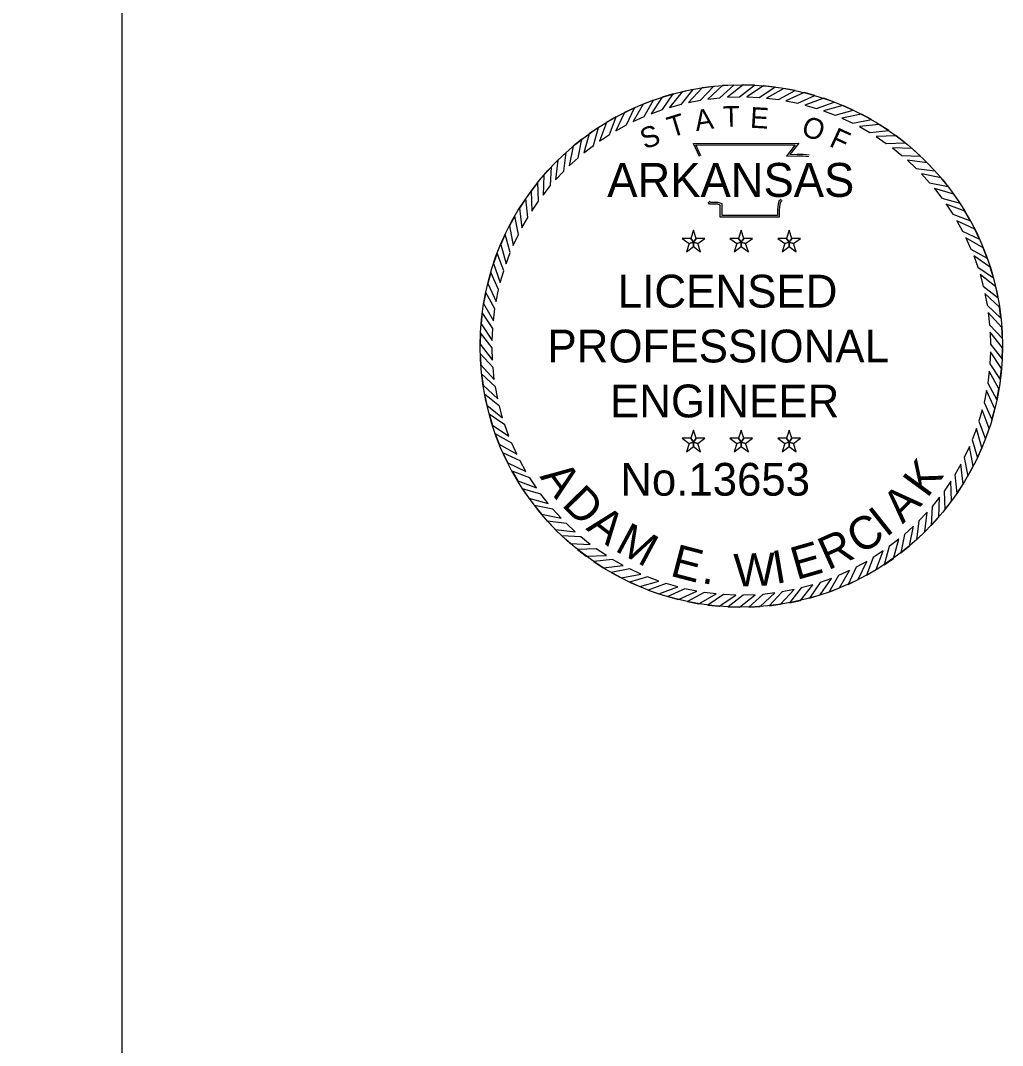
# Model space of a CAD drawing. Extents: x 0 to 19, y -0.6 to 11.2.
# Drawn here: x 16.766 to 19.022, y 5.302 to 7.658 of the extents above; entities that cross this region are included whole.
import ezdxf

# ---------------------------------------------------------------- set-up
doc = ezdxf.new("R2010")
doc.units = 0
for name, color, linetype in [('G-ANNO-STMP-AEW', 7, 'Continuous'), ('G-ANNO-TEXT', 7, 'Continuous'), ('G-Border-Paper', 7, 'Continuous'), ('G-No Plot-Stamp-1', 7, 'Continuous')]:
    doc.layers.add(name, color=color, linetype=linetype)

msp = doc.modelspace()

# ---------------------------------------------------------------- linework, layer by layer
at = {"layer": 'G-ANNO-STMP-AEW'}
for points in [[(18.3115, 7.4993), (18.2862, 7.494), (18.2576, 7.458), (18.2845, 7.4654)], [(18.3581, 7.5062), (18.3325, 7.5029), (18.3011, 7.4693), (18.3285, 7.4745)], [(18.4051, 7.5094), (18.3793, 7.5081), (18.3454, 7.477), (18.3731, 7.4801)], [(18.4522, 7.5089), (18.4264, 7.5096), (18.3902, 7.4813), (18.418, 7.4822)], [(18.4991, 7.5047), (18.4735, 7.5074), (18.4351, 7.4821), (18.463, 7.4808)], [(18.5456, 7.4968), (18.5202, 7.5016), (18.48, 7.4793), (18.5077, 7.4758)], [(18.5913, 7.4853), (18.5664, 7.4921), (18.5245, 7.473), (18.5518, 7.4674)], [(18.2206, 7.4747), (18.1965, 7.4655), (18.1738, 7.4255), (18.1992, 7.437)], [(18.2656, 7.4888), (18.2408, 7.4815), (18.2151, 7.4434), (18.2413, 7.4529)], [(18.6359, 7.4703), (18.6116, 7.479), (18.5684, 7.4632), (18.5952, 7.4555)], [(18.1769, 7.4572), (18.1536, 7.4461), (18.1341, 7.4044), (18.1585, 7.4179)], [(18.6793, 7.4518), (18.6557, 7.4624), (18.6114, 7.4501), (18.6375, 7.4402)], [(18.1347, 7.4362), (18.1123, 7.4234), (18.0962, 7.3803), (18.1195, 7.3956)], [(18.721, 7.43), (18.6984, 7.4423), (18.6532, 7.4336), (18.6784, 7.4217)], [(18.7609, 7.4049), (18.7393, 7.419), (18.6936, 7.4138), (18.7178, 7.4)], [(18.0942, 7.412), (18.0729, 7.3975), (18.0603, 7.3533), (18.0823, 7.3704)], [(18.0558, 7.3848), (18.0357, 7.3686), (18.0266, 7.3235), (18.0472, 7.3423)], [(18.7987, 7.3768), (18.7783, 7.3926), (18.7323, 7.391), (18.7554, 7.3753)], [(18.0197, 7.3545), (18.0009, 7.3368), (17.9953, 7.2912), (18.0144, 7.3115)], [(18.8342, 7.3458), (18.8151, 7.3632), (18.7692, 7.3652), (18.7909, 7.3477)], [(18.8672, 7.3122), (18.8495, 7.3309), (18.8038, 7.3365), (18.8242, 7.3175)], [(17.986, 7.3216), (17.9687, 7.3025), (17.9667, 7.2565), (17.9841, 7.2783)], [(18.8974, 7.276), (18.8812, 7.2961), (18.8361, 7.3053), (18.8549, 7.2847)], [(17.955, 7.2861), (17.9393, 7.2657), (17.9409, 7.2197), (17.9565, 7.2428)], [(18.9247, 7.2376), (18.9101, 7.2589), (18.8659, 7.2716), (18.883, 7.2496)], [(17.9269, 7.2483), (17.9128, 7.2267), (17.918, 7.181), (17.9318, 7.2052)], [(18.9489, 7.1972), (18.936, 7.2196), (18.893, 7.2357), (18.9083, 7.2124)], [(17.9019, 7.2084), (17.8895, 7.1857), (17.8983, 7.1406), (17.9102, 7.1658)], [(18.9698, 7.155), (18.9588, 7.1783), (18.9171, 7.1977), (18.9305, 7.1733)], [(17.88, 7.1666), (17.8695, 7.1431), (17.8818, 7.0988), (17.8916, 7.1248)], [(18.3125, 7.1485), (18.3187, 7.157), (18.3125, 7.176), (18.3064, 7.157)], [(18.4222, 7.1485), (18.4284, 7.157), (18.4222, 7.176), (18.4161, 7.157)], [(18.532, 7.1485), (18.5381, 7.157), (18.532, 7.176), (18.5258, 7.157)], [(18.3125, 7.1485), (18.3064, 7.157), (18.2864, 7.157), (18.3026, 7.1453)], [(18.3125, 7.1485), (18.3026, 7.1453), (18.2964, 7.1263), (18.3125, 7.1381)], [(18.3125, 7.1485), (18.3225, 7.1453), (18.3386, 7.157), (18.3187, 7.157)], [(18.3125, 7.1485), (18.3125, 7.1381), (18.3286, 7.1263), (18.3225, 7.1453)], [(18.4222, 7.1485), (18.4161, 7.157), (18.3962, 7.157), (18.4123, 7.1453)], [(18.4222, 7.1485), (18.4123, 7.1453), (18.4061, 7.1263), (18.4222, 7.1381)], [(18.4222, 7.1485), (18.4322, 7.1453), (18.4483, 7.157), (18.4284, 7.157)], [(18.4222, 7.1485), (18.4222, 7.1381), (18.4384, 7.1263), (18.4322, 7.1453)], [(18.532, 7.1485), (18.5258, 7.157), (18.5059, 7.157), (18.522, 7.1453)], [(18.532, 7.1485), (18.522, 7.1453), (18.5158, 7.1263), (18.532, 7.1381)], [(18.532, 7.1485), (18.5419, 7.1453), (18.5581, 7.157), (18.5381, 7.157)], [(18.532, 7.1485), (18.532, 7.1381), (18.5481, 7.1263), (18.5419, 7.1453)], [(18.9874, 7.1113), (18.9782, 7.1354), (18.9382, 7.158), (18.9496, 7.1326)], [(17.8615, 7.1233), (17.8529, 7.099), (17.8686, 7.0558), (17.8764, 7.0825)], [(19.0015, 7.0663), (18.9942, 7.0911), (18.9561, 7.1168), (18.9655, 7.0905)], [(17.8465, 7.0786), (17.8398, 7.0537), (17.8588, 7.0119), (17.8645, 7.0392)], [(19.012, 7.0204), (19.0067, 7.0456), (18.9707, 7.0742), (18.978, 7.0474)], [(17.835, 7.0329), (17.8303, 7.0076), (17.8526, 6.9674), (17.856, 6.995)], [(19.0188, 6.9738), (19.0155, 6.9993), (18.9819, 7.0307), (18.9871, 7.0033)], [(17.8272, 6.9865), (17.8244, 6.9608), (17.8498, 6.9225), (17.8511, 6.9503)], [(19.022, 6.9267), (19.0207, 6.9525), (18.9897, 6.9864), (18.9927, 6.9587)], [(17.823, 6.9396), (17.8222, 6.9138), (17.8505, 6.8775), (17.8497, 6.9054)], [(19.0215, 6.8796), (19.0223, 6.9054), (18.994, 6.9417), (18.9948, 6.9138)], [(17.8225, 6.8925), (17.8237, 6.8667), (17.8548, 6.8328), (17.8518, 6.8605)], [(19.0173, 6.8327), (19.0201, 6.8584), (18.9947, 6.8967), (18.9934, 6.8689)], [(17.8256, 6.8454), (17.829, 6.8199), (17.8626, 6.7885), (17.8574, 6.8159)], [(19.0095, 6.7863), (19.0142, 6.8116), (18.9919, 6.8518), (18.9884, 6.8242)], [(18.998, 6.7406), (19.0047, 6.7655), (18.9856, 6.8073), (18.98, 6.78)], [(17.8325, 6.7988), (17.8378, 6.7736), (17.8738, 6.745), (17.8665, 6.7718)], [(18.9829, 6.6959), (18.9916, 6.7202), (18.9759, 6.7634), (18.9681, 6.7367)], [(17.843, 6.7529), (17.8503, 6.7281), (17.8884, 6.7024), (17.879, 6.7287)], [(18.3125, 6.6891), (18.3187, 6.6976), (18.3125, 6.7165), (18.3064, 6.6976)], [(18.4222, 6.6891), (18.4284, 6.6976), (18.4222, 6.7165), (18.4161, 6.6976)], [(18.532, 6.6891), (18.5381, 6.6976), (18.532, 6.7165), (18.5258, 6.6976)], [(18.9645, 6.6526), (18.975, 6.6761), (18.9627, 6.7204), (18.9529, 6.6944)], [(17.8571, 6.7079), (17.8663, 6.6838), (17.9063, 6.6612), (17.8949, 6.6866)], [(18.3125, 6.6891), (18.3064, 6.6976), (18.2864, 6.6976), (18.3026, 6.6858)], [(18.3125, 6.6891), (18.3026, 6.6858), (18.2964, 6.6669), (18.3125, 6.6786)], [(18.3125, 6.6891), (18.3225, 6.6858), (18.3386, 6.6976), (18.3187, 6.6976)], [(18.3125, 6.6891), (18.3125, 6.6786), (18.3286, 6.6669), (18.3225, 6.6858)], [(18.4222, 6.6891), (18.4161, 6.6976), (18.3962, 6.6976), (18.4123, 6.6858)], [(18.4222, 6.6891), (18.4123, 6.6858), (18.4061, 6.6669), (18.4222, 6.6786)], [(18.4222, 6.6891), (18.4322, 6.6858), (18.4483, 6.6976), (18.4284, 6.6976)], [(18.4222, 6.6891), (18.4222, 6.6786), (18.4384, 6.6669), (18.4322, 6.6858)], [(18.532, 6.6891), (18.5258, 6.6976), (18.5059, 6.6976), (18.522, 6.6858)], [(18.532, 6.6891), (18.522, 6.6858), (18.5158, 6.6669), (18.532, 6.6786)], [(18.532, 6.6891), (18.5419, 6.6858), (18.5581, 6.6976), (18.5381, 6.6976)], [(18.532, 6.6891), (18.532, 6.6786), (18.5481, 6.6669), (18.5419, 6.6858)], [(18.9426, 6.6108), (18.955, 6.6335), (18.9462, 6.6786), (18.9343, 6.6534)], [(17.8747, 6.6642), (17.8857, 6.6409), (17.9274, 6.6215), (17.914, 6.6459)], [(17.8956, 6.622), (17.9085, 6.5996), (17.9515, 6.5835), (17.9362, 6.6068)], [(18.9176, 6.5709), (18.9317, 6.5925), (18.9265, 6.6382), (18.9127, 6.614)], [(18.8895, 6.5331), (18.9052, 6.5535), (18.9036, 6.5995), (18.888, 6.5764)], [(17.9198, 6.5816), (17.9344, 6.5603), (17.9786, 6.5476), (17.9615, 6.5696)], [(18.8585, 6.4976), (18.8758, 6.5167), (18.8778, 6.5627), (18.8604, 6.5409)], [(17.9471, 6.5432), (17.9633, 6.5231), (18.0083, 6.5139), (17.9896, 6.5345)], [(18.8248, 6.4647), (18.8436, 6.4824), (18.8492, 6.528), (18.8301, 6.5077)], [(17.9773, 6.507), (17.995, 6.4883), (18.0407, 6.4827), (18.0203, 6.5017)], [(18.7887, 6.4344), (18.8088, 6.4506), (18.8179, 6.4957), (18.7973, 6.4769)], [(18.0103, 6.4734), (18.0294, 6.456), (18.0753, 6.454), (18.0536, 6.4715)], [(18.7503, 6.4072), (18.7716, 6.4217), (18.7842, 6.4659), (18.7622, 6.4488)], [(18.0458, 6.4424), (18.0662, 6.4266), (18.1122, 6.4282), (18.0891, 6.4439)], [(18.7098, 6.383), (18.7322, 6.3958), (18.7483, 6.4389), (18.725, 6.4236)], [(18.0836, 6.4143), (18.1052, 6.4002), (18.1509, 6.4054), (18.1267, 6.4192)], [(18.6676, 6.362), (18.6909, 6.3731), (18.7104, 6.4148), (18.6859, 6.4013)], [(18.1235, 6.3892), (18.1461, 6.3769), (18.1913, 6.3856), (18.166, 6.3975)], [(18.6239, 6.3445), (18.648, 6.3537), (18.6707, 6.3937), (18.6453, 6.3822)], [(18.1652, 6.3674), (18.1888, 6.3568), (18.2331, 6.3691), (18.207, 6.379)], [(18.2086, 6.3489), (18.2329, 6.3402), (18.2761, 6.356), (18.2493, 6.3637)], [(18.533, 6.3199), (18.5583, 6.3252), (18.5869, 6.3612), (18.56, 6.3538)], [(18.5789, 6.3304), (18.6037, 6.3377), (18.6294, 6.3758), (18.6032, 6.3663)], [(18.2532, 6.3339), (18.2781, 6.3271), (18.32, 6.3462), (18.2927, 6.3518)], [(18.2989, 6.3224), (18.3243, 6.3176), (18.3645, 6.3399), (18.3368, 6.3434)], [(18.3454, 6.3145), (18.371, 6.3118), (18.4094, 6.3371), (18.3815, 6.3384)], [(18.3923, 6.3103), (18.4181, 6.3096), (18.4543, 6.3379), (18.4265, 6.337)], [(18.4394, 6.3098), (18.4652, 6.3111), (18.4991, 6.3422), (18.4714, 6.3391)], [(18.4864, 6.313), (18.512, 6.3163), (18.5434, 6.3499), (18.516, 6.3447)]]:
    msp.add_lwpolyline(points, close=True, dxfattribs=at)
for points in [[(18.3261, 7.3451), (18.3121, 7.3754), (18.5542, 7.3755), (18.5339, 7.3501), (18.5504, 7.3503), (18.5641, 7.3505), (18.5778, 7.349)], [(18.3296, 7.3467), (18.3181, 7.3716), (18.5462, 7.3717), (18.5259, 7.3462), (18.5504, 7.3465), (18.5639, 7.3467), (18.5774, 7.3452)], [(18.516, 7.2437), (18.5119, 7.2403), (18.5105, 7.2353), (18.5091, 7.2227), (18.5091, 7.206), (18.374, 7.206), (18.374, 7.2286), (18.374, 7.2336), (18.3686, 7.2353), (18.3493, 7.2353), (18.3459, 7.2405)], [(18.5136, 7.2466), (18.5085, 7.2425), (18.5067, 7.236), (18.5053, 7.223), (18.5053, 7.2099), (18.3779, 7.2099), (18.3779, 7.2286), (18.3779, 7.2365), (18.3691, 7.2391), (18.3514, 7.2391), (18.3491, 7.2426)]]:
    msp.add_lwpolyline(points, dxfattribs=at)
at = {"layer": 'G-Border-Paper'}
msp.add_lwpolyline([(17, 11), (0, 11), (0, 0), (17, 0)], close=True, dxfattribs=at)
at = {"layer": 'G-No Plot-Stamp-1'}
msp.add_circle((18.4222, 6.9096), 0.6, dxfattribs=at)

# ---------------------------------------------------------------- texts
at = {"layer": 'G-ANNO-TEXT'}
for s, height, rotation, p in [('T', 0.0477, 16.9015, (18.2608, 7.3882)), ('A', 0.0477, 8.6788, (18.3187, 7.4034)), ('T', 0.0477, 1.4789, (18.3804, 7.4129)), ('E', 0.0477, 356.672, (18.4415, 7.4114)), ('O', 0.0477, 341.2218, (18.5574, 7.395)), ('S', 0.0477, 19.7726, (18.2001, 7.361)), ('F', 0.0477, 335.3628, (18.6218, 7.3699)), ('K', 0.0754, 53.8471, (18.8495, 6.5585)), ('A', 0.0754, 305.982, (17.958, 6.6093)), ('D', 0.0754, 314.3022, (18.0075, 6.5441)), ('A', 0.0754, 45.185, (18.7929, 6.4994)), ('A', 0.0754, 322.6223, (18.0634, 6.4889)), ('I', 0.0754, 38.4057, (18.7549, 6.4687)), ('M', 0.0754, 331.7969, (18.1293, 6.4402)), ('C', 0.0754, 32.1396, (18.695, 6.4289)), ('R', 0.0754, 24.1616, (18.6211, 6.3937)), ('E', 0.0754, 16.0125, (18.5491, 6.3716)), ('E', 0.0754, 345.2782, (18.2564, 6.3823)), ('W', 0.0754, 2.1127, (18.4063, 6.3565)), ('I', 0.0754, 9.5753, (18.5011, 6.363)), ('.', 0.0754, 350.8583, (18.3296, 6.3653))]:
    msp.add_text(s, height=height, rotation=rotation, dxfattribs=at).set_placement(p)
for s, height, p in [('ARKANSAS', 0.07792, (18.1143, 7.2524)), ('LICENSED', 0.07543, (18.1385, 6.998)), ('PROFESSIONAL', 0.075433, (17.9768, 6.8719)), ('ENGINEER', 0.07543, (18.1205, 6.7457)), ('No.13653', 0.07514, (18.1443, 6.5659))]:
    msp.add_text(s, height=height, dxfattribs=at).set_placement(p)

doc.saveas('drawing.dxf')
